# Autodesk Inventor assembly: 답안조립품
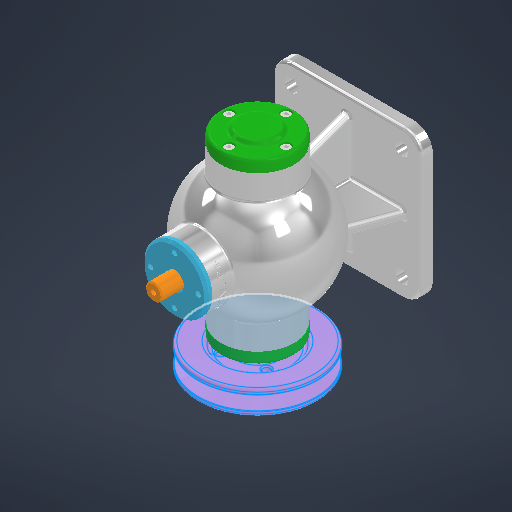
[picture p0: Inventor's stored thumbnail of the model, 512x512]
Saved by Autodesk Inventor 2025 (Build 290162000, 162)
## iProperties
Created: 2025-08
Part Number: 답안조립품
Document SubType Name: Assembly
Designer: infra10
Author: infra10
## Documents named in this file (15)
- C:\Users\infra10\Desktop\750807V1011\답안조립품.iam
- C:\Users\infra10\Desktop\750807V1011\본체.ipt
- C:\Users\infra10\Desktop\750807V1011\V-벨트풀리\V-벨트풀리.ipt
- C:\Users\infra10\Desktop\750807V1011\너트 M8\너트 M8.ipt
- C:\Users\infra10\Desktop\750807V1011\뒤커버\뒤커버.ipt
- C:\Users\infra10\Desktop\750807V1011\베어링- 6202\베어링- 6202.ipt
- C:\Users\infra10\Desktop\750807V1011\볼트 M4 x 12\볼트 M4 x 12.ipt
- C:\Users\infra10\Desktop\750807V1011\볼트 M4 x 16\볼트 M4 x 16.ipt
- C:\Users\infra10\Desktop\750807V1011\상부커버\상부커버.ipt
- C:\Users\infra10\Desktop\750807V1011\슬라이드\슬라이드.ipt
- C:\Users\infra10\Desktop\750807V1011\앞커버\앞커버.ipt
- C:\Users\infra10\Desktop\750807V1011\오일실 15 30 7\오일실 15 30 7.ipt
- C:\Users\infra10\Desktop\750807V1011\칼라\칼라.ipt
- C:\Users\infra10\Desktop\750807V1011\키 4 x 4 x 12\키 4 x 4 x 12.ipt
- C:\Users\infra10\Desktop\750807V1011\편심축\편심축.ipt
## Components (1 placed, 1 different names)
1. V-벨트풀리:1
